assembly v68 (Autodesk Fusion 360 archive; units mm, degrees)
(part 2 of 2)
sketch "Sketch9" plane through (0, 0, 27.75) normal (0, 0, 1) x axis (1, 0, 0)
  line L1 (0.3547, 3.5) -> (4, 3.5)
  line L2 (7.5, 23.915) -> (0.3547, 3.5)
  line L3 (7.5, 7) -> (7.5, 23.915)
  line L4 (-0.624, 37.8701) -> (-6.8287, 43.0612)
  line L5 (-7.5, 24.118) -> (-0.624, 37.8701)
  line L6 (-7.5, 41) -> (-7.5, 24.118)
  line L7 (0, 38.6519) -> (6.128, 43.7788)
  line L8 (-6.128, 43.7788) -> (0, 38.6519)
  line L9 (4, 44.5) -> (-4, 44.5)
  line L10 (-9, 38) -> (-9, 44)
  curve K1 (-13.1231, 36) -> (-9, 38)
  line L11 (-27.8876, 33) -> (-27.8876, 35)
  curve K2 (-19.7703, 32) -> (-20.811, 33)
  line L12 (-9, 11) -> (-9, 24)
  curve K3 (-14, 8.2866) -> (-9, 11)
  line L13 (-14, 0) -> (-14, 8.2866)
  line L14 (14, 0) -> (-14, 0)
  line L15 (14, 8.2866) -> (14, 0)
  curve K4 (9, 11) -> (14, 8.2866)
  line L16 (9, 22) -> (9, 11)
  curve K5 (21.8452, 32) -> (9, 22)
  line L17 (58.6876, 35) -> (58.6876, 33)
  curve K6 (13.1231, 36) -> (14.3385, 35)
  line L18 (9, 44) -> (9, 38)
  line L19 (7.5, 24.118) -> (7.5, 41)
  line L20 (0.624, 37.8701) -> (7.5, 24.118)
  line L21 (6.8287, 43.0612) -> (0.624, 37.8701)
  line L22 (0, 36.882) -> (-6.191, 24.5)
  line L23 (6.191, 24.5) -> (0, 36.882)
  line L24 (-6.191, 24.5) -> (6.191, 24.5)
  line L25 (-6.2953, 23.5) -> (0, 5.5135)
  line L26 (6.2953, 23.5) -> (-6.2953, 23.5)
  line L27 (0, 5.5135) -> (6.2953, 23.5)
  line L28 (-7.5, 23.915) -> (-7.5, 7)
  line L29 (-0.3547, 3.5) -> (-7.5, 23.915)
  line L30 (-4, 3.5) -> (-0.3547, 3.5)
  curve K7
  curve K8
  curve K9
  curve K10
  line L31 (38.25, 47) -> (14.3385, 47)
  line L32 (38.25, 48) -> (38.25, 47)
  line L33 (-16.25, 48) -> (38.25, 48)
  line L34 (-16.25, 47) -> (-16.25, 48)
  line L35 (-14.3385, 47) -> (-16.25, 47)
  curve K11 (-13.1231, 46) -> (-14.3385, 47)
  curve K12 (-9, 44) -> (-13.1231, 46)
  curve K13 (-14.3385, 35) -> (-13.1231, 36)
  line L36 (-27.8876, 35) -> (-14.3385, 35)
  line L37 (-20.811, 33) -> (-27.8876, 33)
  curve K14 (-9, 24) -> (-19.7703, 32)
  curve K15 (22.8744, 33) -> (21.8452, 32)
  line L38 (58.6876, 33) -> (22.8744, 33)
  line L39 (14.3385, 35) -> (58.6876, 35)
  curve K16 (9, 38) -> (13.1231, 36)
  curve K17 (13.1231, 46) -> (9, 44)
  curve K18 (14.3385, 47) -> (13.1231, 46)
  arc A1 centre (4, 7) radius 3.5 clockwise from (7.5, 7) to (4, 3.5)
  arc A2 centre (-4, 41) radius 3.5 clockwise from (-7.5, 41) to (-6.8287, 43.0612)
  arc A3 centre (-4, 41) radius 3.5 clockwise from (-6.128, 43.7788) to (-4, 44.5)
  arc A4 centre (4, 41) radius 3.5 clockwise from (4, 44.5) to (6.128, 43.7788)
  arc A5 centre (4, 41) radius 3.5 clockwise from (6.8287, 43.0612) to (7.5, 41)
  arc A6 centre (-4, 7) radius 3.5 clockwise from (-4, 3.5) to (-7.5, 7)
  point P1 (0, 0)
  dimension "d145" distance K8 K10 = 5
  dimension "d146" distance K7 K9 = 6
  dimension "d158" distance P1 = 27
  dimension "d159" distance P1 K10 = 10
  dimension "d144" Text1-Height = 5
extrude "Extrude14" cut sketch "Sketch9" against normal blind 1

design "Raspberry PI Zero W"
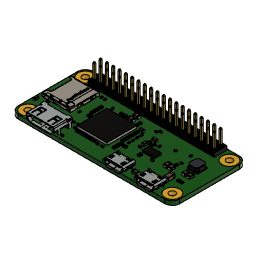
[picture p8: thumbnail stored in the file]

design "macro_0.67xwideangle_lens"
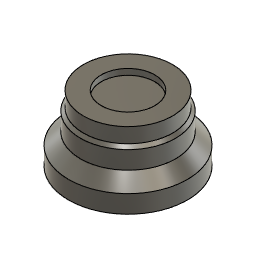
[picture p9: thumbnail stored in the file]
sketch "Sketch1" plane through (0, 0, 0) normal (1, 0, 0) x axis (0, 0, -1)
  line L1 (0, 11) -> (0, 0)
  line L2 (10, 0) -> (0, 0)
  line L3 (10, 3) -> (10, 0)
  line L4 (8, 5) -> (10, 3)
  line L5 (8, 8) -> (8, 5)
  line L6 (7.5, 8.5) -> (8, 8)
  line L7 (7.5, 11) -> (7.5, 8.5)
  line L8 (0, 11) -> (7.5, 11)
  point P1 (0, 0)
  point P2 (0, 0)
  point P4 (0, 0)
  point P3 (0, 11)
  point P5 (10, 0)
  point P6 (10, 3)
  point P7 (8, 5)
  point P8 (8, 8)
  point P10 (7.5, 11)
  coincident P1 P2
  vertical L1
  coincident P1 P4
  perpendicular L1 L2
  perpendicular L2 L3
  perpendicular L2 L5
  parallel L4 L6
  parallel L5 L7
  horizontal L8
  dimension "d1" distance P2 P3 = 11
  dimension "d2" distance P4 P5 = 10 (= "( 20 / 2 ) * 1 mm")
  dimension "d3" distance P5 P6 = 3
  dimension "d4" distance P7 P8 = 3
  dimension "d5" distance P3 P7 = 6
  dimension "d6" distance P3 P10 = 7.5 (= "( 15 / 2 ) * 1 mm")
  dimension "d7" distance L1 L5 = 8 (= "( 16 / 2 ) * 1 mm")
revolve "Revolve1" sketch "Sketch1" AlongAngle 360
sketch "Sketch2" plane through (0, 0, 0) normal (0, -1, 0) x axis (1, 0, 0)
  circle C1 centre (0, 0) radius 10
  circle C2 centre (0, 0) radius 6.5
  concentric C1 C2
  dimension "d9" diameter C2 = 13
extrude "Extrude1" cut sketch "Sketch2" profile of C2 against normal blind 1
chamfer "Chamfer1" distance 1
sketch "Sketch3" plane through (0, 11, 0) normal (0, 1, 0) x axis (-1, 0, 0)
  circle C1 centre (0, 0) radius 7.5
  circle C2 centre (0, 0) radius 4.5
  point P1 (0, 0)
  point P3 (0, 0)
  coincident P1 P3
  dimension "d13" diameter C2 = 9
extrude "Extrude2" cut sketch "Sketch3" profile of C2 against normal blind 1

design "Wemos Battery Shield V3"
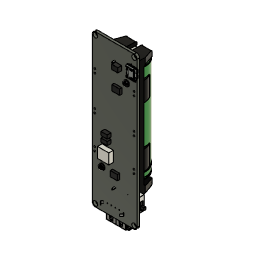
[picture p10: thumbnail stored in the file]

design "camera_mounting_shroud"
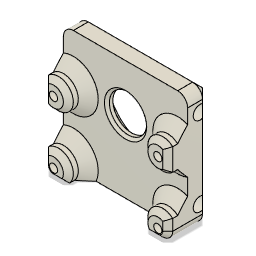
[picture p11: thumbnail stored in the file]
sketch "Sketch1" plane through (0, 0, 0) normal (0, 0, 1) x axis (1, 0, 0)
  line L1 (10.5, 12) -> (-10.5, 12)
  line L2 (12.5, -10) -> (12.5, 10)
  line L3 (-10.5, -12) -> (10.5, -12)
  line L4 (-12.5, 10) -> (-12.5, -10)
  line L5 (12.5, 0) -> (-12.5, 0)
  line L6 (0, 12) -> (0, -12)
  arc A1 centre (-10.5, 10) radius 2 clockwise from (-12.5, 10) to (-10.5, 12)
  arc A2 centre (10.5, 10) radius 2 clockwise from (10.5, 12) to (12.5, 10)
  arc A3 centre (10.5, -10) radius 2 clockwise from (12.5, -10) to (10.5, -12)
  arc A4 centre (-10.5, -10) radius 2 clockwise from (-10.5, -12) to (-12.5, -10)
  circle C1 centre (-10.5, -10) radius 1
  circle C2 centre (10.5, -10) radius 1
  circle C3 centre (-10.5, 2.5) radius 1
  circle C4 centre (10.5, 2.5) radius 1
  circle C5 centre (-10.5, -10) radius 0.825
  circle C6 centre (10.5, -10) radius 0.825
  circle C7 centre (-10.5, 2.5) radius 0.825
  circle C8 centre (10.5, 2.5) radius 0.825
  arc A5 centre (-10.5, 2.5) radius 3 clockwise from (-12.5, 4.7361) to (-12.5, 0.2639)
  arc A6 centre (-10.5, -10) radius 3 clockwise from (-12.5, -7.7639) to (-8.2639, -12)
  arc A7 centre (10.5, -10) radius 3 clockwise from (8.2639, -12) to (12.5, -7.7639)
  arc A8 centre (10.5, 2.5) radius 3 clockwise from (12.5, 0.2639) to (12.5, 4.7361)
  point P6 (0, 0)
  point P1 (0, 0)
  point P5 (0, 12)
  point P2 (-12.5, 0)
  point P3 (12.5, 0)
  point P4 (0, -12)
  point P19 (-10.5, -10)
  point P21 (-10.5, 2.5)
  point P31 (-12.5, 4.7361)
  point P32 (-12.5, 0.2639)
  point P33 (-12.5, -7.7639)
  point P34 (-8.2639, -12)
  point P35 (8.2639, -12)
  point P36 (12.5, -7.7639)
  point P37 (12.5, 0.2639)
  point P38 (12.5, 4.7361)
  horizontal L1
  vertical L2
  horizontal L3
  vertical L4
  coincident L5 P6
  coincident L6 P6
  coincident P1 P6
  coincident L1 P5
  coincident L4 P2
  tangent L1 A1
  tangent L4 A1
  coincident L2 P3
  tangent L1 A2
  tangent L2 A2
  equal A1 A2
  coincident L3 P4
  tangent L2 A3
  tangent L3 A3
  equal A1 A3
  tangent L3 A4
  tangent L4 A4
  equal A1 A4
  horizontal L5
  vertical L6
  midpoint L5 P6
  midpoint P1 L6
  symmetric L6 C1 C2
  equal C1 C3
  vertical P19 P21
  symmetric L6 C3 C4
  concentric C1 C5
  symmetric L6 C5 C6
  concentric C3 C7
  equal C5 C7
  symmetric L6 C7 C8
  concentric C1 A6
  concentric C6 A7
  concentric C8 A8
  concentric C7 A5
  equal A5 A8
  equal A7 A8
  equal A6 A7
  coincident L4 P31
  coincident L4 P32
  coincident L4 P33
  coincident L3 P34
  coincident L3 P35
  coincident L2 P36
  coincident L2 P37
  coincident L2 P38
  dimension "d1" distance P2 P3 = 25
  dimension "d2" distance P4 P5 = 24
  dimension "d3" radius A1 = 2
  dimension "d4" diameter C1 = 2
  dimension "d5" distance L3 P19 = 2
  dimension "d6" distance L4 P19 = 2
  dimension "d8" distance P19 P21 = 12.5
  dimension "d9" diameter C5 = 1.65
  dimension "d10" diameter A6 = 6
extrude "Extrude3" new body sketch "Sketch1" profile of L1 L2 L3 L4 A1 A2 A3 A4 C5 C6 C7 C8 A6 A7 A8 A5 along normal blind 5
extrude "Extrude4" sketch "Sketch1" profile of L2 L3 L4 A3 A4 C5 C6 C7 C8 A6 A7 A8 A5 blind 4
sketch "Sketch2" plane through (12.5, 0, 0) normal (1, 0, 0) x axis (0, 0, -1)
  line L1 (0, 10) -> (0, -10)
  line L2 (-5, 10) -> (0, 10)
  line L3 (-5, 4.7361) -> (-5, 10)
  line L4 (-9, -7.7639) -> (-5, -7.7639)
  line L5 (-2.5, -8) -> (-2.5, 10)
  line L6 (-9, -12) -> (-5, -12)
  line L7 (-5, 12) -> (0, 12)
  line L8 (-9, 4.7361) -> (-5, 4.7361)
  line L9 (-9, 0.2639) -> (-9, 4.7361)
  line L10 (-5, 0.2639) -> (-9, 0.2639)
  line L11 (-5, -7.7639) -> (-5, 0.2639)
  line L12 (0, -10) -> (-9, -10)
  line L13 (-9, -12) -> (0, -12)
  circle C1 centre (-2.5, 8) radius 1.375
  circle C2 centre (-2.5, -8) radius 1.375
  point P9 (-2.5, 10)
  point P8 (-2.5, -8)
  point P7 (-2.5, 8)
  point P10 (-2.5, -8)
  midpoint L2 P9
  coincident P8 L5
  coincident P7 L5
  coincident P8 P10
  vertical L5
  equal C1 C2
  dimension "d21" diameter C1 = 2.75
  dimension "d22" distance P8 L6 = 4
  dimension "d23" distance P7 L7 = 4
extrude "Extrude5" cut sketch "Sketch2" profile of C1 C2 against normal blind 5
mirror "Mirror1" mirrorStitchTolerance 0.1
sketch "Sketch3" plane through (0, 0, 0) normal (0, 0, -1) x axis (-1, 0, 0)
  line L1 (-12.5, -10) -> (-12.5, 10)
  line L2 (10.5, -12) -> (-10.5, -12)
  line L3 (12.5, 10) -> (12.5, -10)
  line L4 (-10.5, 12) -> (10.5, 12)
  line L5 (4.25, 6.8) -> (-4.25, 6.8)
  line L6 (4.25, -1.7) -> (4.25, 6.8)
  line L7 (-4.25, -1.7) -> (4.25, -1.7)
  line L8 (-4.25, 6.8) -> (-4.25, -1.7)
  line L9 (4.25, -1.7) -> (-4.25, 6.8)
  line L10 (-4.25, -1.7) -> (4.25, 6.8)
  arc A1 centre (-10.5, 10) radius 2 clockwise from (-12.5, 10) to (-10.5, 12)
  arc A2 centre (-10.5, -10) radius 2 clockwise from (-10.5, -12) to (-12.5, -10)
  arc A3 centre (10.5, -10) radius 2 clockwise from (12.5, -10) to (10.5, -12)
  arc A4 centre (10.5, 10) radius 2 clockwise from (10.5, 12) to (12.5, 10)
  circle C1 centre (0, 2.55) radius 3.75
  circle C2 centre (0, 2.55) radius 7.65
  point P19 (0, 2.55)
  point P14 (0, 2.55)
  point P1 (0, 0)
  point P20 (0, 2.55)
  point P15 (-4.25, 6.8)
  point P16 (4.25, 6.8)
  horizontal L5
  perpendicular L5 L6
  parallel L5 L7
  parallel L6 L8
  coincident L9 P19
  coincident L10 P19
  coincident P14 P19
  equal L5 L6
  vertical P1 P14
  coincident P19 P20
  dimension "d44" diameter C1 = 7.5
  dimension "d45" distance P15 P16 = 8.5
  dimension "d46" distance L4 L5 = 5.2
  dimension "d47" diameter C2 = 15.3
extrude "Extrude7" cut sketch "Sketch3" profile of C1 to an object
extrude "Extrude8" cut sketch "Sketch3" profile of C1 L5 L6 L7 L8 C2 against normal blind 3.45 (magnitude of "-3.3 mm - 0.15 mm")
sketch "Sketch4" plane through (0, 0, 3.45) normal (0, 0, -1) x axis (-1, 0, 0)
  circle C1 centre (0, 2.55) radius 3.75
  circle C2 centre (0, 2.55) radius 6.55
  circle C3 centre (0, 2.55) radius 7.65
  point P2 (0, 2.55)
  point P3 (0, 2.55)
  coincident P2 P3
  dimension "d53" diameter C2 = 13.1
extrude "Extrude9" cut sketch "Sketch4" profile of C1 C2 against normal blind 0.35
chamfer "Chamfer1" distance 2 distance 2 distance 0.5 distance 1
chamfer "Chamfer2" distance 1
named bodies: "cam_mount"

design "fisheye_lens_180degFoV"
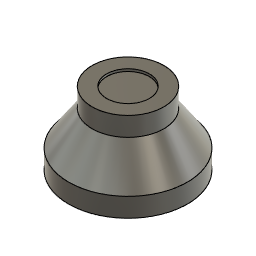
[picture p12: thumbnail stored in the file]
sketch "Sketch1" plane through (0, 0, 0) normal (1, 0, 0) x axis (0, 0, -1)
  line L1 (0, 15.25) -> (0, 0)
  line L2 (12.5, 0) -> (0, 0)
  line L3 (12.5, 4) -> (12.5, 0)
  line L4 (7.55, 11.25) -> (7.55, 15.25)
  line L5 (12.5, 4) -> (7.55, 11.25)
  line L6 (0, 15.25) -> (7.55, 15.25)
  point P1 (0, 0)
  point P2 (0, 0)
  point P4 (0, 0)
  point P3 (0, 15.25)
  point P7 (7.55, 15.25)
  point P5 (12.5, 0)
  point P6 (12.5, 4)
  point P8 (7.55, 11.25)
  coincident P1 P2
  vertical L1
  coincident P1 P4
  perpendicular L1 L2
  perpendicular L2 L3
  parallel L3 L4
  horizontal P3 P7
  dimension "d1" distance P2 P3 = 15.25
  dimension "d2" distance P1 P5 = 12.5 (= "( 25 / 2 ) * 1 mm")
  dimension "d3" distance P5 P6 = 4
  dimension "d4" distance P7 P8 = 4
  dimension "d5" distance P3 P7 = 7.55 (= "( 15.1 / 2 ) * 1 mm")
revolve "Revolve1" sketch "Sketch1" AlongAngle 360
sketch "Sketch2" plane through (0, 0, 0) normal (0, -1, 0) x axis (1, 0, 0)
  circle C1 centre (0, 0) radius 12.5
  circle C2 centre (0, 0) radius 10
  concentric C1 C2
  dimension "d7" diameter C2 = 20
extrude "Extrude1" cut sketch "Sketch2" profile of C2 against normal blind 0.5
sketch "Sketch3" plane through (0, 15.25, 0) normal (0, 1, 0) x axis (-1, 0, 0)
  circle C1 centre (0, 0) radius 7.55
  circle C2 centre (0, 0) radius 4.5
  point P1 (0, 0)
  point P3 (0, 0)
  coincident P1 P3
  dimension "d10" diameter C2 = 9
extrude "Extrude2" cut sketch "Sketch3" profile of C2 against normal blind 0.5

design "lens_mount_adapter_maglock"
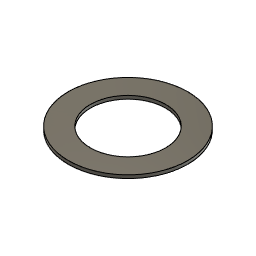
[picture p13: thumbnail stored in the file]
sketch "Sketch1" plane through (0, 0, 0) normal (0, 1, 0) x axis (1, 0, 0)
  circle C1 centre (0, 0) radius 4.1
  circle C2 centre (0, 0) radius 6.5
  point P1 (0, 0)
  point P2 (0, 0)
  coincident P1 P2
  concentric C1 C2
  dimension "d1" diameter C1 = 8.2
  dimension "d2" diameter C2 = 13
extrude "Extrude1" new body sketch "Sketch1" along normal blind 0.35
